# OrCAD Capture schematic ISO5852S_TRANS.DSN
size D
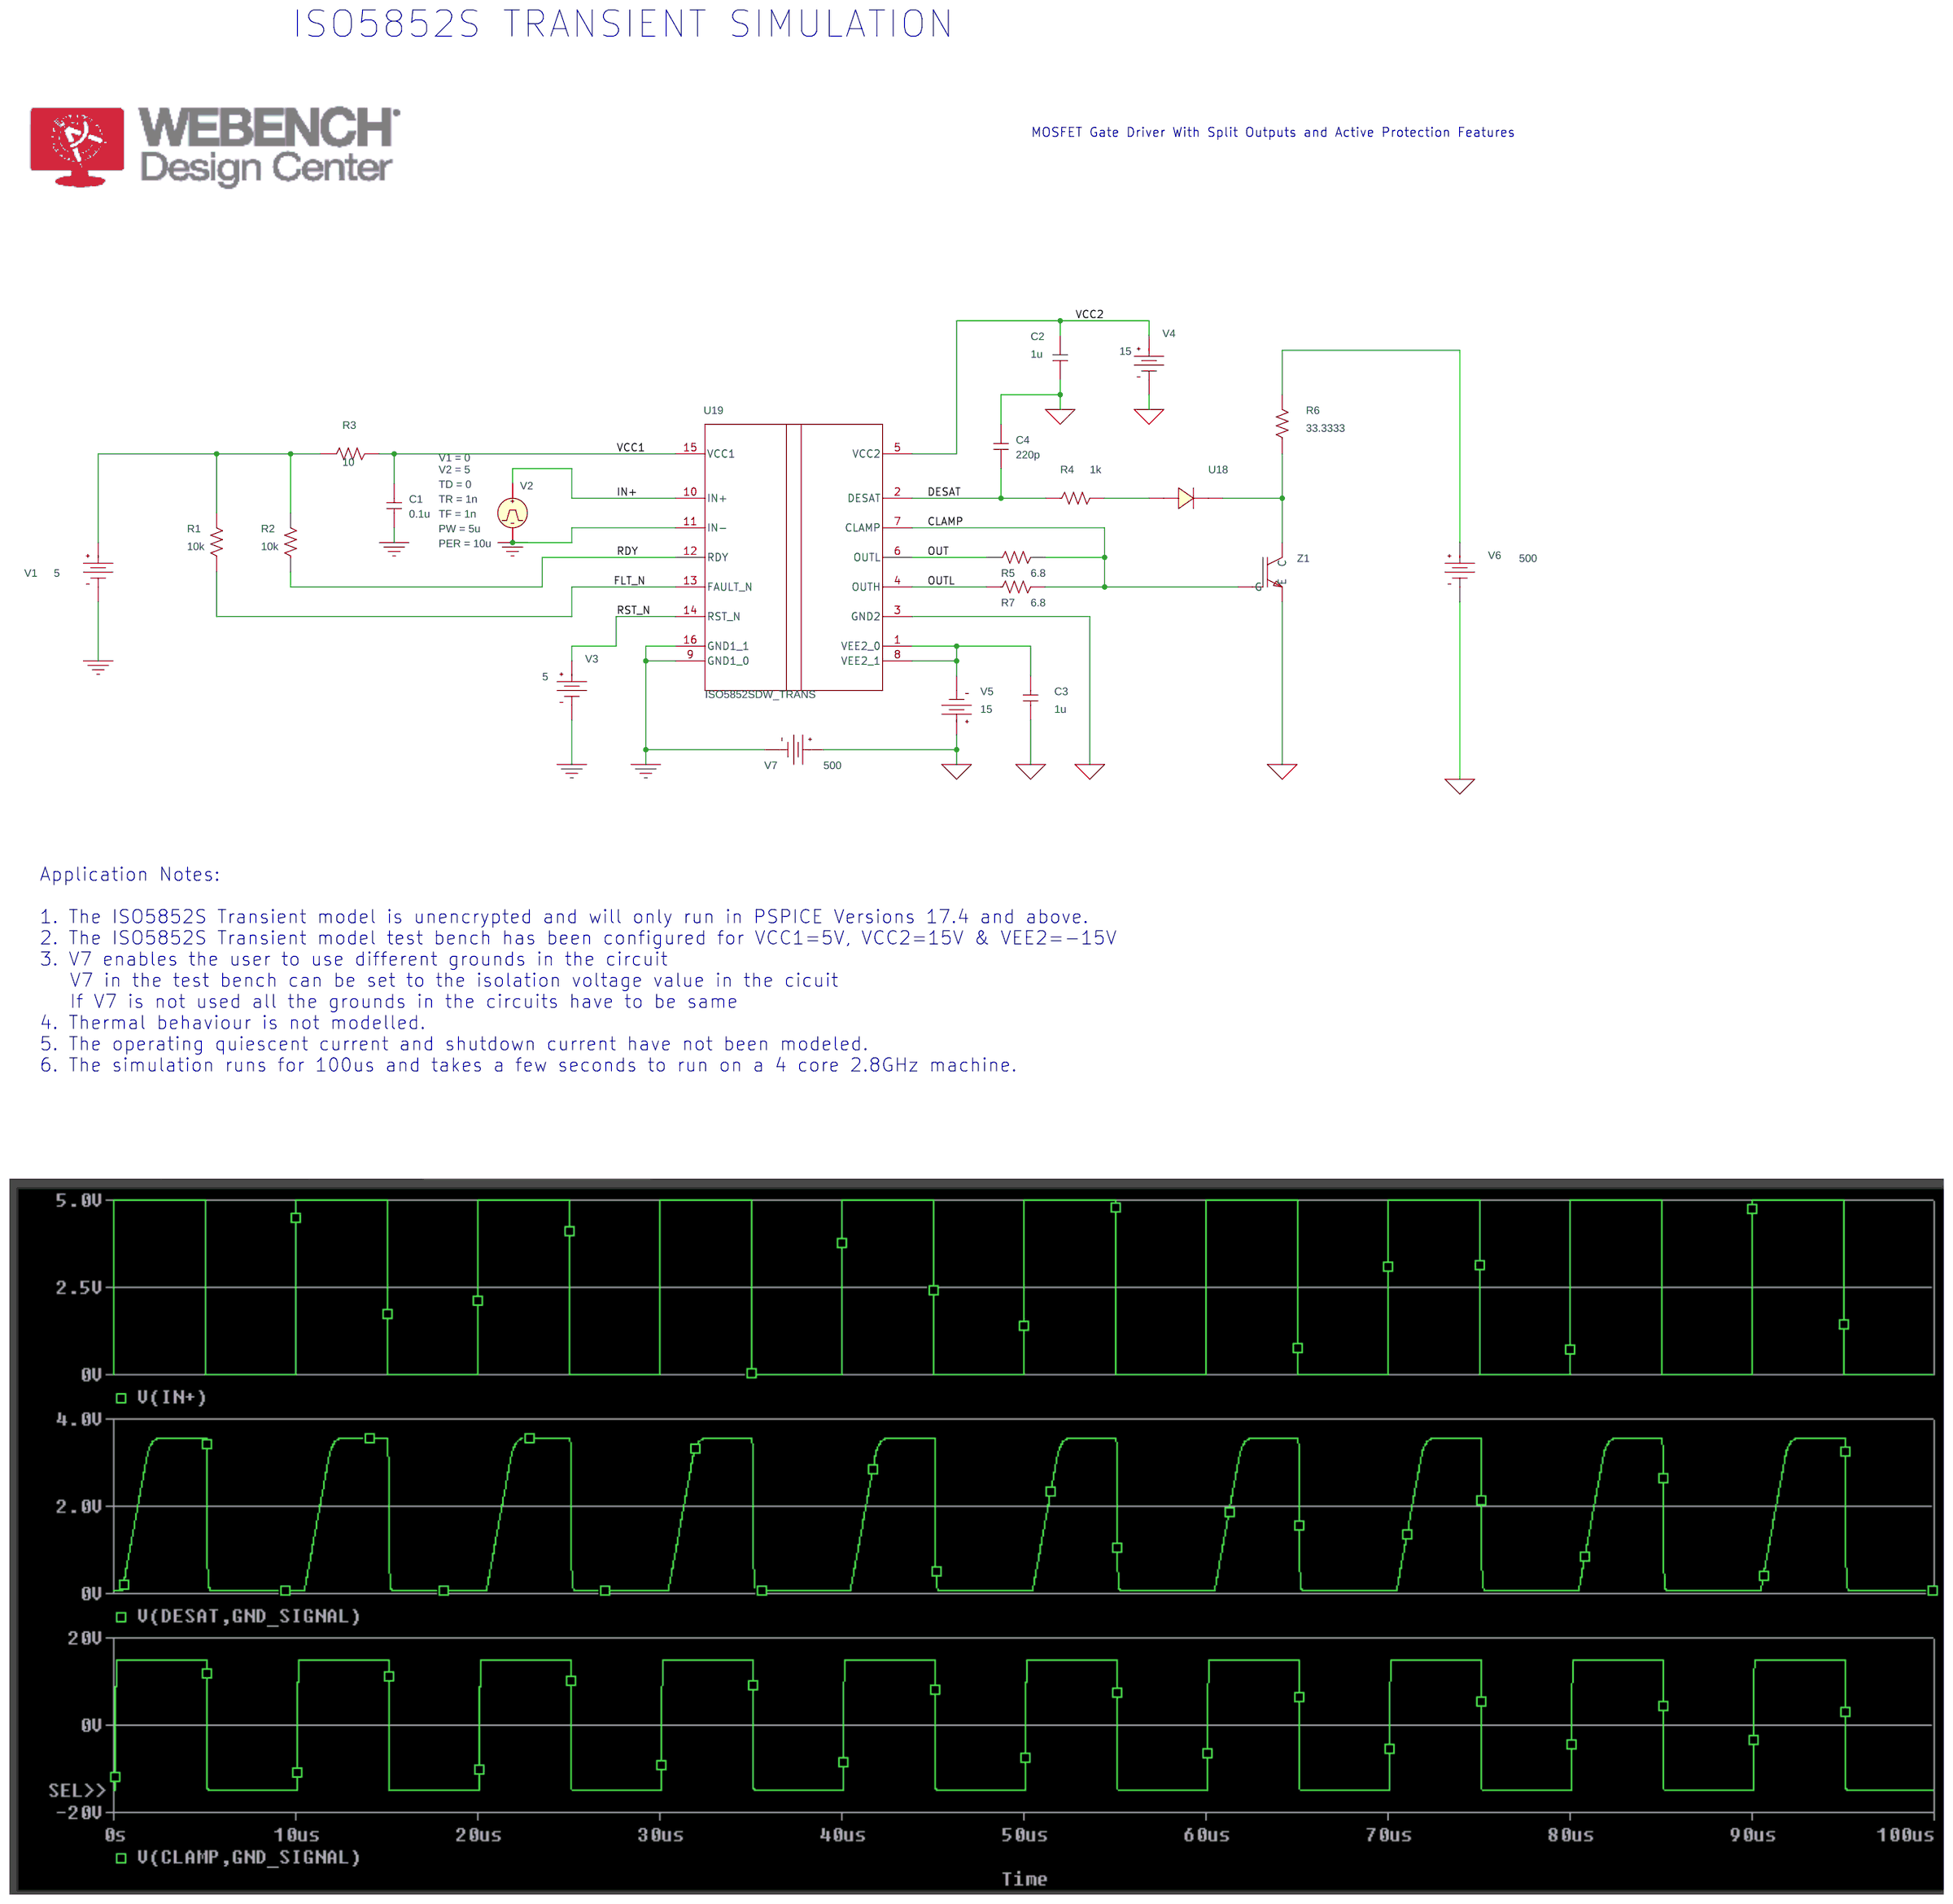
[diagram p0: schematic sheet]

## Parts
C1  0.1u  [RAD/CK05]
C2  1u  [RAD/CK05]
C3  1u  [RAD/CK05]
C4  220p  [RAD/CK05]
R1  10k  [AX/RC05]
R2  10k  [AX/RC05]
R3  10  [AX/RC05]
R4  1k  [AX/RC05]
R5  6.8  [AX/RC05]
R6  33.3333  [AX/RC05]
R7  6.8  [AX/RC05]
U18  D_D1
U19  ISO5852SDW_TRANS  [DW0016B_N]
V1  VDC
V2  VPULSE
V3  VDC
V4  VDC
V5  VDC
V6  VDC
V7  VDC
Z1  IXGA8N100  [TO-263]

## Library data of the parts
C1-C4 = C
R1-R7 = R
U18 = D_D1
U19 = ISO5852SDW_TRANS
V1 V3 = VDC: DC: 5
V2 = VPULSE: PER: 10u; PW: 5u; TD: 0; TF: 1n; TR: 1n; V1: 0; V2: 5
V4 V5 = VDC: DC: 15
V6 V7 = VDC: DC: 500
Z1 = IXGA8N100

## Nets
GND_SIGNAL: C2.1 C3.1 C4.2 U19.3(GND2) V4.1(-) V5.0(+) V6.1(-) V7.0(+) Z1.3(E)
VCC1: C1.2 R3.2 U19.15(VCC1)
VCC2: C2.2 U19.5(VCC2) V4.0(+)
0: C1.1 U19.9(GND1_0) U19.11(IN-) U19.16(GND1_1) V1.1(-) V2.2(-) V3.1(-) V7.1(-)
CLAMP: R5.2 R7.2 U19.7(CLAMP) Z1.1(G)
DESAT: C4.1 R4.1 U19.2(DESAT)
FLT_N: R1.1 U19.13(FAULT_N)
IN+: U19.10(IN+) V2.1(+)
OUT: R5.1 U19.6(OUTL)
OUTL: R7.1 U19.4(OUTH)
RDY: R2.1 U19.12(RDY)
RST_N: U19.14(RST_N) V3.0(+)
N16731106: R1.2 R2.2 R3.1 V1.0(+)
N16731342: R6.1 U18.2 Z1.2(C)
N16731354: C3.2 U19.1(VEE2_0) U19.8(VEE2_1) V5.1(-)
N16731676: R4.2 U18.1
N16731822: R6.2 V6.0(+)

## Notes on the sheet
- ISO5852S TRANSIENT SIMULATION
- MOSFET Gate Driver With Split Outputs and Active Protection Features
- Application Notes:
  1. The ISO5852S Transient model is unencrypted and will only run in PSPICE Versions 17.4 and above.
  2. The ISO5852S Transient model test bench has been configured for VCC1=5V, VCC2=15V & VEE2=-15V
  3. V7 enables the user to use different grounds in the circuit
     V7 in the test bench can be set to the isolation voltage value in the cicuit
     If V7 is not used all the grounds in the circuits have to be same
  4. Thermal behaviour is not modelled.
  5. The operating quiescent current and shutdown current have not been modeled.
  6. The simulation runs for 100us and takes a few seconds to run on a 4 core 2.8GHz machine.
